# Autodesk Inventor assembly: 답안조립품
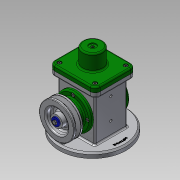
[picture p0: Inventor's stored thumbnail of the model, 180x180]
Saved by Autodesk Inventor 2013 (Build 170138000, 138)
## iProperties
Created: 2019-08
Part Number: 답안조립품
Document SubType Name: Assembly
Designer: hana-cad17
Author: hana-cad17
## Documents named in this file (18)
- C:\Documents and Settings\hana-cad17\바탕 화면\490804V1003\답안조립품.iam
- C:\Documents and Settings\hana-cad17\바탕 화면\490804V1003\본체.ipt
- C:\Documents and Settings\hana-cad17\바탕 화면\490804V1003\편심축.ipt
- C:\Documents and Settings\hana-cad17\바탕 화면\490804V1003\베어링 17 x 40 x 12.ipt
- C:\Documents and Settings\hana-cad17\바탕 화면\490804V1003\뒤커버.ipt
- C:\Documents and Settings\hana-cad17\바탕 화면\490804V1003\앞커버.ipt
- C:\Documents and Settings\hana-cad17\바탕 화면\490804V1003\오일 실 17 30 8.ipt
- C:\Documents and Settings\hana-cad17\바탕 화면\490804V1003\키 4 x 4 x 12.ipt
- C:\Documents and Settings\hana-cad17\바탕 화면\490804V1003\V-벨트풀리.ipt
- C:\Documents and Settings\hana-cad17\바탕 화면\490804V1003\와셔 4x16.ipt
- C:\Documents and Settings\hana-cad17\바탕 화면\490804V1003\볼트 M4 x 10.ipt
- C:\Documents and Settings\hana-cad17\바탕 화면\490804V1003\슬라이더.ipt
- C:\Documents and Settings\hana-cad17\바탕 화면\490804V1003\클레비스 핀 6 x 22.ipt
- 클레비스 핀 6 x 22.ipt
- C:\Documents and Settings\hana-cad17\바탕 화면\490804V1003\E-링.ipt
- C:\Documents and Settings\hana-cad17\바탕 화면\490804V1003\링크.ipt
- C:\Documents and Settings\hana-cad17\바탕 화면\490804V1003\덮개.ipt
- C:\Documents and Settings\hana-cad17\바탕 화면\490804V1003\볼트 M4 x 8.ipt
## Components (2 placed, 2 different names)
1. V-벨트풀리:1 — 각도:2
2. E-링:1
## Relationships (1: Angle 1)
- 각도:2 [Angle]: V-벨트풀리:1
